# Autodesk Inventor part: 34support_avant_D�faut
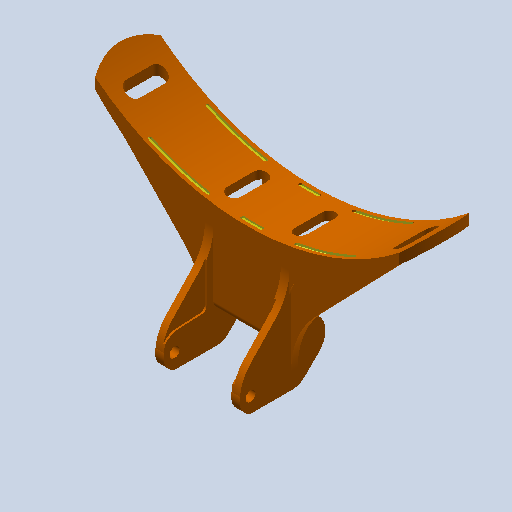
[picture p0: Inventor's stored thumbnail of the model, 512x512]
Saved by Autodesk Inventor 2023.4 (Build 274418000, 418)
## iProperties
Created: 2011-01
Part Number: 34support_avant_D�faut
Document SubType Name: Modeling
Designer: eric
Density: 1 g/cm^3
Mass: 82.6929 g
Surface Area: 397.904 cm^2
Volume: 82.6929 cm^3
Material: Générique
Appearance: 255,128,0
Author: eric
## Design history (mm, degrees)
feature "Base1"
node "Corps solides"
node "Corps surfaciques"
node "Solide1"
